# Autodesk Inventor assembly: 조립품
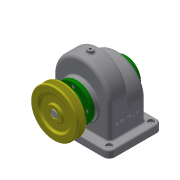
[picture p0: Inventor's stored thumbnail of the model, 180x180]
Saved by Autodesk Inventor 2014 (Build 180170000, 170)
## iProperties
Created: 2017-11
Part Number: 조립품
Document SubType Name: Assembly
Designer: user
Author: user
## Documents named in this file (14)
- C:\Users\user\Desktop\471108V1008\조립품.iam
- C:\Users\user\Desktop\471108V1008\본체.ipt
- C:\Users\user\Desktop\471108V1008\축.ipt
- C:\Users\user\Desktop\471108V1008\앞커버.ipt
- C:\Users\user\Desktop\471108V1008\뒤커버.ipt
- C:\Users\user\Desktop\471108V1008\스퍼기어.ipt
- C:\Users\user\Desktop\471108V1008\볼트 M3 x 8.ipt
- C:\Users\user\Desktop\471108V1008\키 - 6 x 6 x 22.ipt
- C:\Users\user\Desktop\471108V1008\키 - 5 x 5 x 18.ipt
- C:\Users\user\Desktop\471108V1008\멈춤나사 - M4 x 10.ipt
- 멈춤나사 - M4 x 10.ipt
- C:\Users\user\Desktop\471108V1008\베어링 6002.ipt
- C:\Users\user\Desktop\471108V1008\V-벨트풀리.ipt
- C:\Users\user\Desktop\471108V1008\오일 실 15 30 7.ipt
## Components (1 placed, 1 different names)
1. V-벨트풀리:1
